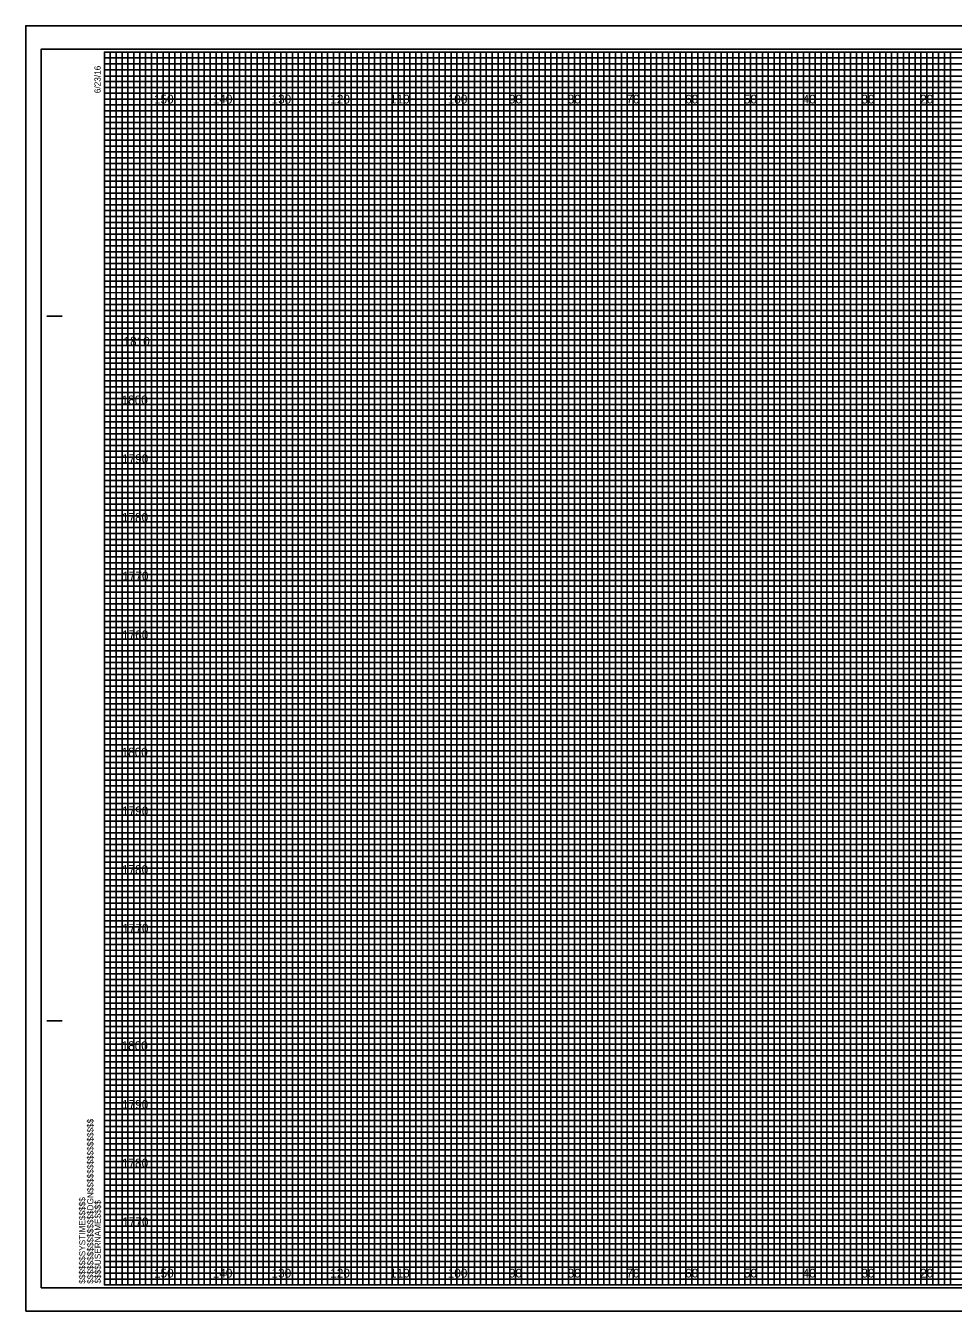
# Model space of a CAD drawing. Extents: x -13 to 323, y -5 to 434.
# Drawn here: x -13.4 to 144.5, y 215.5 to 434.5 of the extents above; entities that cross this region are included whole.
import ezdxf

# ---------------------------------------------------------------- set-up
doc = ezdxf.new("R2010")
doc.units = 0
for name, color, linetype in [('Old_Level_62', 7, 'Continuous'), ('Pattern 1', 7, 'Continuous'), ('Pattern 4', 7, 'Continuous'), ('Pattern 5', 7, 'Continuous'), ('Prop Dimension', 7, 'Continuous'), ('Prop Horizontal Alignment', 7, 'Continuous'), ('Prop PHM Label Text', 7, 'Continuous'), ('Scratch_Level_0', 7, 'Continuous'), ('Scratch_Level_2', 7, 'Continuous'), ('Scratch_Level_3', 7, 'Continuous'), ('Scratch_Level_5', 7, 'Continuous')]:
    doc.layers.add(name, color=color, linetype=linetype)

msp = doc.modelspace()

# ---------------------------------------------------------------- linework, layer by layer
at = {"layer": 'Old_Level_62'}
for p, q in [((0, 429), (260, 429)), ((260, 427.98), (0, 427.98)), ((0, 427.98), (0, 427)), ((0, 427), (260, 427)), ((260, 425.89), (0, 425.89)), ((0, 425.89), (0, 424)), ((0, 424), (320, 424))]:
    msp.add_line(p, q, dxfattribs=at)
for points in [[(0, 423), (270, 423), (320, 423), (320, 422), (0, 422)], [(0, 421), (320, 421), (320, 419), (0, 419)], [(0, 418), (320, 418), (320, 417), (0, 416.98)], [(0, 416), (320, 416), (320, 414), (0, 414)], [(0, 413), (320, 413), (320, 412), (0, 412)], [(0, 411), (320, 411), (320, 409), (0, 409)], [(0, 408), (320, 408), (320, 407), (0, 407)], [(0, 406), (320, 406), (320, 404), (0, 404)], [(0, 403), (320, 403), (320, 402), (0, 402)], [(0, 401), (320, 401), (320, 399), (0, 399)], [(0, 398), (320, 398), (320, 397), (0, 397)], [(0, 396), (320, 396), (320, 393.95), (320, 393), (320, 392), (0, 392)], [(0, 394), (320, 394), (320, 393), (0, 393)], [(0, 391), (320, 391), (320, 389), (0, 389.03)], [(0, 389.03), (320, 389), (320, 388), (0, 388)], [(0, 387), (320, 387), (320, 386), (0, 386)], [(0, 384), (320, 384), (320, 383), (0, 383)], [(0, 382), (320, 382), (320, 381), (0, 381)], [(-0.07, 378.89), (320, 378.89), (320, 377.88), (-0.07, 377.88)], [(0, 377), (320, 377), (320, 376), (0, 376)], [(0, 374), (320, 374), (320, 373), (0, 373)], [(0, 372), (320, 372), (320, 371), (0, 371)], [(0, 369), (320, 369), (320, 368), (0, 368)], [(0, 367), (320, 367), (320, 366), (0, 366)], [(0, 364), (320, 364), (320, 363), (0, 363)], [(0, 362), (320, 362), (320, 361), (0, 361)], [(0, 359), (320, 359), (319.99, 357.98), (0, 358)], [(0, 357), (320, 357), (320, 356), (0, 356)], [(0, 354), (320, 354), (320, 353), (0, 353)], [(0, 352), (320, 352), (320, 351), (0, 351)], [(0, 349), (320, 349), (320, 348), (0, 348)], [(0, 347), (320, 347), (320, 346), (0, 346)], [(0, 344), (320, 344), (320, 343), (0, 343)], [(0, 342), (320, 342), (320, 341), (0, 341)], [(0, 339), (320, 339), (320, 338), (0, 338)], [(0, 336.99), (320.07, 336.91), (320, 336), (0, 336)], [(0, 334), (320, 334), (320, 333), (0, 333)], [(0, 332), (320, 332), (320, 331), (0, 331)], [(0, 329), (320, 329), (320, 328), (0, 328)], [(0, 327), (320, 327), (320, 326), (0, 326)], [(0, 324), (320, 324), (320, 323), (0, 323)], [(0, 322), (320, 322), (320, 321), (0, 321)], [(0, 319), (320, 319), (320, 318), (0, 318)], [(0, 317), (320, 317), (320, 316), (0, 316)], [(0, 314), (320, 314), (320, 313), (0, 313)], [(0, 312), (320, 312), (320, 311), (0, 311)], [(0, 309), (320, 309), (320, 308), (0, 308)], [(0, 307), (320, 307), (320, 306), (0, 306)], [(0, 304), (320, 304), (320, 303), (0, 303)], [(0, 302), (320, 302), (320, 301), (0, 301)], [(0, 299), (320, 299), (319.99, 297.98), (0, 298)], [(0, 297), (320, 297), (320, 296), (0, 296)], [(0, 294), (320, 294), (320, 293), (0, 293)], [(0, 292), (320, 292), (320, 291), (0, 291)], [(0, 289), (320, 289), (320, 288), (0, 288)], [(0, 287), (320, 287), (320, 286), (0, 286)], [(0, 284), (320, 284), (320, 283), (0, 283)], [(0, 282), (320, 282), (320, 281), (0, 281)], [(0, 279), (320, 279), (320, 278), (0, 278)], [(0, 276.99), (320.07, 276.91), (320, 276), (0, 276)], [(0, 274), (320, 274), (320, 273), (0, 273)], [(0, 272), (320, 272), (320, 271), (0, 271)], [(0, 269), (320, 269), (320, 268), (0, 268)], [(0, 267), (320, 267), (320, 266), (0, 266)], [(0, 264), (320, 264), (320, 263), (0, 263)], [(0, 262), (320, 262), (320, 261), (0, 261)], [(0, 259), (320, 259), (320, 258), (0, 258)], [(0, 257), (320, 257), (320, 256), (0, 256)], [(0, 254), (320, 254), (320, 253), (0, 253)], [(0, 252), (320, 252), (320, 251), (0, 251)], [(0, 249), (320, 249), (320, 248), (0, 248)], [(0, 247), (320, 247), (320, 246), (0, 246)], [(0, 244), (320, 244), (320, 243), (0, 243)], [(0, 242), (320, 242), (320, 241), (0, 241)], [(0, 239), (320, 239), (320, 238), (0, 238)], [(0, 237), (320, 237), (320, 236), (0, 236)], [(0, 234), (320, 234), (320, 233), (0, 233)], [(0, 232), (320, 232), (320, 231), (0, 231)], [(0, 229), (320, 229), (320, 228), (0, 228)], [(0, 227), (320, 227), (320, 226), (0, 226)], [(0, 224), (320, 224), (320, 223), (0, 223)], [(0, 222), (320, 222), (320, 221), (0, 221)]]:
    msp.add_lwpolyline(points, dxfattribs=at)
at = {"layer": 'Pattern 1'}
for p, q in [((323.3, 434.5), (-13.4, 434.5)), ((-13.4, 434.5), (-13.4, 215.5)), ((-13.4, 215.5), (323.3, 215.5))]:
    msp.add_line(p, q, dxfattribs=at)
at = {"layer": 'Pattern 4'}
for points in [[(0, 430), (5, 430), (5, 220), (15, 220), (15, 430), (25, 430), (25, 220), (35, 220), (35, 430), (45, 430), (45, 220), (55, 220), (55, 430), (65, 430), (65, 220), (75, 220), (75, 430), (85, 430), (85, 220), (95, 220), (95, 430), (105, 430), (105, 220), (115, 220), (115, 430), (125, 430), (125, 220), (135, 220), (135, 430), (145, 430)], [(0, 425), (275, 425)], [(0, 405), (320, 405), (320, 415), (0, 415)], [(0, 385), (320, 385), (320, 395), (0, 395)], [(0, 365), (320, 365), (320, 375), (0, 375)], [(0, 345), (320, 345), (320, 355), (0, 355)], [(0, 325), (320, 325), (320, 335), (0, 335)], [(0, 305), (320, 305), (320, 315), (0, 315)], [(0, 285), (320, 285), (320, 295), (0, 295)], [(0, 265), (320, 265), (320, 275), (0, 275)], [(0, 245), (320, 245), (320, 255), (0, 255)], [(0, 225), (320, 225), (320, 235), (0, 235)]]:
    msp.add_lwpolyline(points, dxfattribs=at)
at = {"layer": 'Pattern 5'}
for p, q in [((10, 220), (10, 430)), ((20, 220), (20, 430)), ((30, 220), (30, 430)), ((40, 220), (40, 430)), ((50, 220), (50, 430)), ((60, 220), (60, 430)), ((70, 220), (70, 430)), ((80, 220), (80, 430)), ((90, 220), (90, 430)), ((100, 220), (100, 430)), ((110, 220), (110, 430)), ((120, 220), (120, 430)), ((130, 220), (130, 430)), ((140, 220), (140, 430)), ((0, 420), (320, 420)), ((0, 410), (320, 410)), ((0, 400), (320, 400)), ((0, 390), (320, 390)), ((0, 380), (320, 380)), ((0, 370), (320, 370)), ((0, 360), (320, 360)), ((0, 350), (320, 350)), ((0, 340), (320, 340)), ((0, 330), (320, 330)), ((0, 320), (320, 320)), ((0, 310), (320, 310)), ((0, 300), (320, 300)), ((0, 290), (320, 290)), ((0, 280), (320, 280)), ((0, 270), (320, 270)), ((0, 260), (320, 260)), ((0, 250), (320, 250)), ((0, 240), (320, 240)), ((0, 230), (320, 230))]:
    msp.add_line(p, q, dxfattribs=at)
at = {"layer": 'Prop Dimension'}
for p, q in [((-9.8, 385), (-7.3, 385)), ((-9.7, 385), (-7.2, 385)), ((-9.8, 265), (-7.3, 265)), ((-9.7, 265), (-7.2, 265)), ((0, 220), (0, 220)), ((0, 220), (0, 220)), ((0, 220), (0, 220)), ((0, 220), (0, 220)), ((0, 220), (0, 220)), ((0, 220), (0, 220)), ((0, 220), (0, 220))]:
    msp.add_line(p, q, dxfattribs=at)
msp.add_lwpolyline([(320, 430), (0, 430), (0, 220), (320, 220)], close=True, dxfattribs=at)
at = {"layer": 'Prop Horizontal Alignment'}
for p, q in [((10, 430), (0, 430)), ((10, 220), (10, 430)), ((30, 430), (20, 430)), ((20, 430), (20, 220)), ((30, 220), (30, 430)), ((50, 430), (40, 430)), ((40, 430), (40, 220)), ((50, 220), (50, 430)), ((70, 430), (60, 430)), ((60, 430), (60, 220)), ((70, 220), (70, 430)), ((90, 430), (80, 430)), ((80, 430), (80, 220)), ((90, 220), (90, 430)), ((110, 430), (100, 430)), ((100, 430), (100, 220)), ((110, 220), (110, 430)), ((130, 430), (120, 430)), ((120, 430), (120, 220)), ((130, 220), (130, 430)), ((150, 430), (140, 430)), ((140, 430), (140, 220)), ((20, 220), (10, 220)), ((40, 220), (30, 220)), ((60, 220), (50, 220)), ((80, 220), (70, 220)), ((100, 220), (90, 220)), ((120, 220), (110, 220)), ((140, 220), (130, 220))]:
    msp.add_line(p, q, dxfattribs=at)
for points in [[(0, 420), (320, 420), (320, 410), (0, 410)], [(0, 400), (320, 400), (320, 390), (0, 390)], [(0, 380), (320, 380), (320, 370), (0, 370)], [(0, 360), (320, 360), (320, 350), (0, 350)], [(0, 340), (320, 340), (320, 330), (0, 330)], [(0, 320), (320, 320), (320, 310), (0, 310)], [(0, 300), (320, 300), (320, 290), (0, 290)], [(0, 280), (320, 280), (320, 270), (0, 270)], [(0, 260), (320, 260), (320, 250), (0, 250)], [(0, 240), (320, 240), (320, 230), (0, 230)]]:
    msp.add_lwpolyline(points, dxfattribs=at)
at = {"layer": 'Prop PHM Label Text'}
for points in [[(0, 220), (1, 220), (1, 430), (2, 430), (2, 220)], [(2, 220), (3, 220), (3, 430), (4, 430), (4, 220)], [(5, 220), (6, 220), (6, 430), (7, 430), (7, 220)], [(7, 220), (8, 220), (8, 430), (9, 430), (9, 220)], [(10, 220), (11, 220), (11, 430), (12, 430), (12, 220)], [(12, 220), (13, 220), (13, 430), (14, 430), (14, 220)], [(15, 220), (16, 220), (16, 430), (17, 430), (17, 220)], [(17, 220), (18, 220), (18, 430), (19, 430), (19, 220)], [(20, 220), (21, 220), (21, 430), (22, 430), (22, 220)], [(22, 220), (23, 220), (23, 430), (24, 430), (24, 220)], [(25, 220), (26, 220), (26, 430), (27, 430), (27, 220)], [(27, 220), (28, 220), (28, 430), (29, 430), (29, 220)], [(30, 220), (31, 220), (31, 430), (32, 430), (32, 220)], [(32, 220), (33, 220), (33, 430), (34, 430), (34, 220)], [(35, 220), (36, 220), (36, 430), (37, 430), (37, 220)], [(37, 220), (38, 220), (38, 430), (39, 430), (39, 220)], [(40, 220), (41, 220), (41, 430), (42, 430), (42, 220)], [(42, 220), (43, 220), (43, 430), (44, 430), (44, 220)], [(45, 220), (46, 220), (46, 430), (47, 430), (47, 220)], [(47, 220), (48, 220), (48, 430), (49, 430), (49, 220)], [(50, 220), (51, 220), (51, 430), (52, 430), (52, 220)], [(52, 220), (53, 220), (53, 430), (54, 430), (54, 220)], [(55, 220), (56, 220), (56, 430), (57, 430), (57, 220)], [(57, 220), (58, 220), (58, 430), (59, 430), (59, 220)], [(60, 220), (61, 220), (61, 430), (62, 430), (62, 220)], [(62, 220), (63, 220), (63, 430), (64, 430), (64, 220)], [(65, 220), (66, 220), (66, 430), (67, 430), (67, 220)], [(67, 220), (68, 220), (68, 430), (69, 430), (69, 220)], [(70, 220), (71, 220), (71, 430), (72, 430), (72, 220)], [(72, 220), (73, 220), (73, 430), (74, 430), (74, 220)], [(75, 220), (76, 220), (76, 430), (77, 430), (77, 220)], [(77, 220), (78, 220), (78, 430), (79, 430), (79, 220)], [(80, 220), (81, 220), (81, 430), (82, 430), (82, 220)], [(82, 220), (83, 220), (83, 430), (84, 430), (84, 220)], [(85, 220), (86, 220), (86, 430), (87, 430), (87, 220)], [(87, 220), (88, 220), (88, 430), (89, 430), (89, 220)], [(90, 220), (91, 220), (91, 430), (92, 430), (92, 220)], [(92, 220), (93, 220), (93, 430), (94, 430), (94, 220)], [(95, 220), (96, 220), (96, 430), (97, 430), (97, 220)], [(97, 220), (98, 220), (98, 430), (99, 430), (99, 220)], [(100, 220), (101, 220), (101, 430), (102, 430), (102, 220)], [(102, 220), (103, 220), (103, 430), (104, 430), (104, 220)], [(105, 220), (106, 220), (106, 430), (107, 430), (107, 220)], [(107, 220), (108, 220), (108, 430), (109, 430), (109, 220)], [(110, 220), (111, 220), (111, 430), (112, 430), (112, 220)], [(112, 220), (113, 220), (113, 430), (114, 430), (114, 220)], [(115, 220), (116, 220), (116, 430), (117, 430), (117, 220)], [(117, 220), (118, 220), (118, 430), (119, 430), (119, 220)], [(120, 220), (121, 220), (121, 430), (122, 430), (122, 220)], [(122, 220), (123, 220), (123, 430), (124, 430), (124, 220)], [(125, 220), (126, 220), (126, 430), (127, 430), (127, 220)], [(127, 220), (128, 220), (128, 430), (129, 430), (129, 220)], [(130, 220), (131, 220), (131, 430), (132, 430), (132, 220)], [(132, 220), (133, 220), (133, 430), (134, 430), (134, 220)], [(135, 220), (136, 220), (136, 430), (137, 430), (137, 220)], [(137, 220), (138, 220), (138, 430), (139, 430), (139, 220)], [(140, 220), (141, 220), (141, 430), (142, 430), (142, 220)], [(142, 220), (143, 220), (143, 430), (144, 430), (144, 220)]]:
    msp.add_lwpolyline(points, dxfattribs=at)
at = {"layer": 'Scratch_Level_0'}
msp.add_lwpolyline([(-10.8, 219.5), (322.4, 219.5), (322.4, 430.5), (-10.8, 430.5)], close=True, dxfattribs=at)
at = {"layer": 'Scratch_Level_5'}
msp.add_lwpolyline([(-13.4, 215.5), (323.3, 215.5), (323.3, 434.5), (-13.4, 434.5)], close=True, dxfattribs=at)

# ---------------------------------------------------------------- texts
at = {"layer": 'Prop Dimension'}
for s, p in [('6/23/16', (-0.65, 423)), ('$$$$$$$$$$$$$$$$DGN$$$$$$$$$$$$$$$$', (-1.88, 220.18)), ('$$$$$$SYSTIME$$$$$', (-3.26, 220.18)), ('$$$$USERNAME$$$$', (-0.62, 220.23))]:
    msp.add_text(s, height=1.05, rotation=90, dxfattribs=at).set_placement(p)
at = {"layer": 'Scratch_Level_2'}
for s, p in [('1810', (3.25, 380)), ('1800', (2.92, 370)), ('1790', (3, 360)), ('1780', (2.98, 350)), ('1770', (3.04, 340)), ('1760', (3, 330)), ('1800', (2.92, 310)), ('1790', (3, 300)), ('1780', (2.98, 290)), ('1770', (3.04, 280)), ('1800', (2.92, 260)), ('1790', (3, 250)), ('1780', (2.98, 240)), ('1770', (3.04, 230))]:
    msp.add_text(s, height=1.5, dxfattribs=at).set_placement(p)
at = {"layer": 'Scratch_Level_3'}
for s, p in [('150', (8.44, 421.25)), ('140', (18.44, 421.25)), ('130', (28.44, 421.25)), ('120', (38.44, 421.25)), ('110', (48.62, 421.25)), ('100', (58.44, 421.25)), ('90', (68.86, 421.25)), ('80', (78.86, 421.25)), ('70', (88.86, 421.25)), ('60', (98.86, 421.25)), ('50', (108.86, 421.25)), ('40', (118.86, 421.25)), ('30', (128.86, 421.25)), ('20', (138.86, 421.25)), ('150', (8.44, 221.25)), ('140', (18.44, 221.25)), ('130', (28.44, 221.25)), ('120', (38.44, 221.25)), ('110', (48.62, 221.25)), ('100', (58.44, 221.25)), ('90', (68.86, 221.25)), ('80', (78.86, 221.25)), ('70', (88.86, 221.25)), ('60', (98.86, 221.25)), ('50', (108.86, 221.25)), ('40', (118.86, 221.25)), ('30', (128.86, 221.25)), ('20', (138.86, 221.25))]:
    msp.add_text(s, height=1.5, dxfattribs=at).set_placement(p)

doc.saveas('drawing.dxf')
